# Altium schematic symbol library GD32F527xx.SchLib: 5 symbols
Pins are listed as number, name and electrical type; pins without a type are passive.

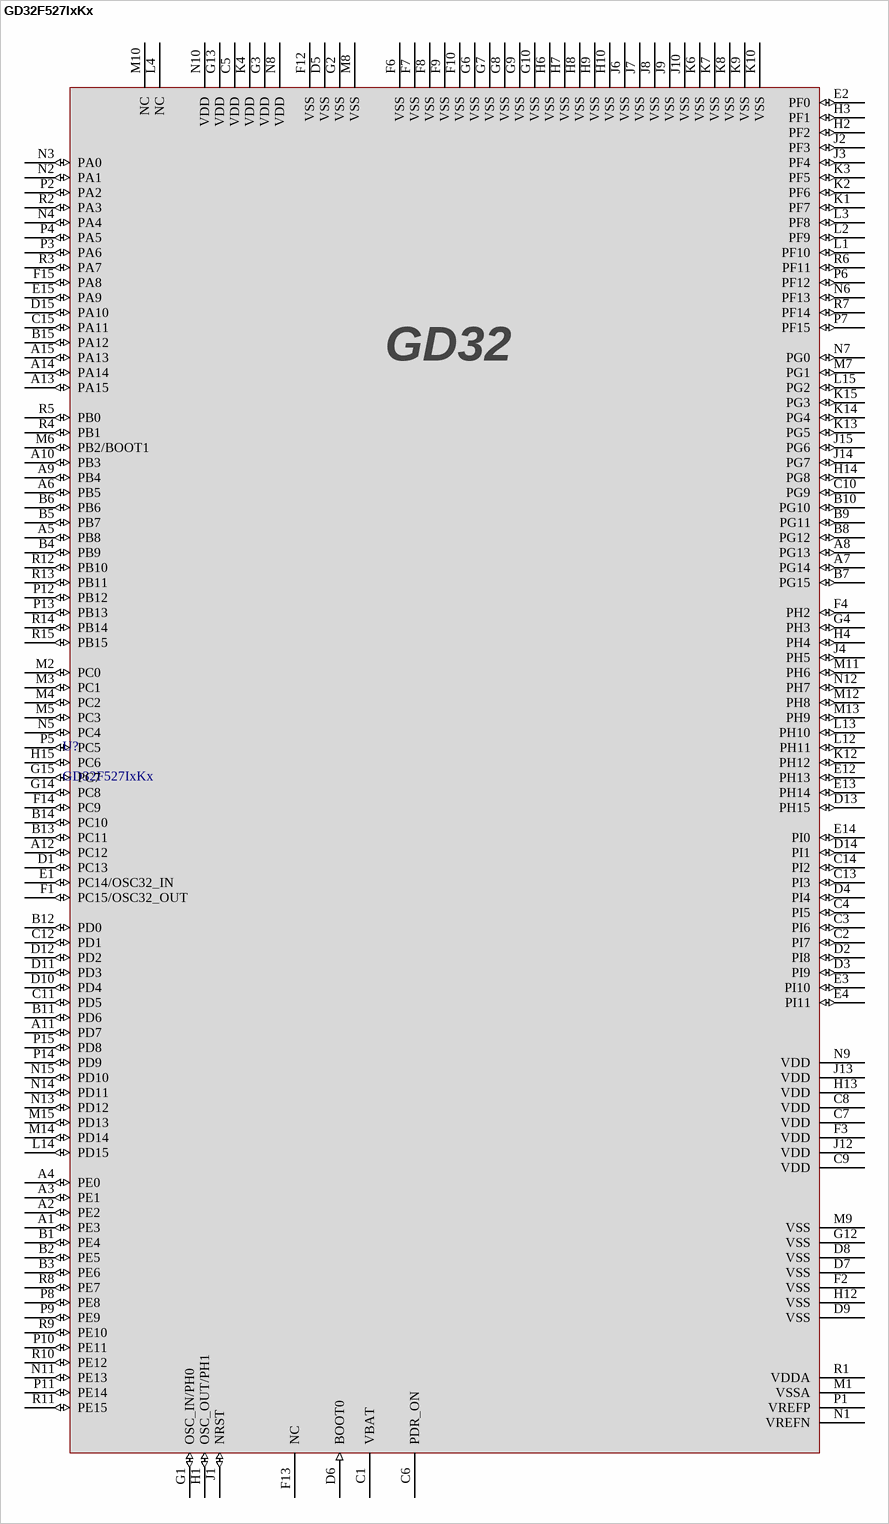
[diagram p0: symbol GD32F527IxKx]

## GD32F527IxKx
designator U?
footprint BGA176_10x10X0.89
pins: A1 PE3 (io), A2 PE2 (io), A3 PE1 (io), A4 PE0 (io), A5 PB8 (io), A6 PB5 (io), A7 PG14 (io), A8 PG13 (io), A9 PB4 (io), A10 PB3 (io), A11 PD7 (io), A12 PC12 (io), A13 PA15 (io), A14 PA14 (io), A15 PA13 (io), B1 PE4 (io), B2 PE5 (io), B3 PE6 (io), B4 PB9 (io), B5 PB7 (io), B6 PB6 (io), B7 PG15 (io), B8 PG12 (io), B9 PG11 (io), B10 PG10 (io), B11 PD6 (io), B12 PD0 (io), B13 PC11 (io), B14 PC10 (io), B15 PA12 (io), C1 VBAT (power), C2 PI7 (io), C3 PI6 (io), C4 PI5 (io), C5 VDD (power), C6 PDR_ON (power), C7 VDD (power), C8 VDD (power), C9 VDD (power), C10 PG9 (io), C11 PD5 (io), C12 PD1 (io), C13 PI3 (io), C14 PI2 (io), C15 PA11 (io), D1 PC13 (io), D2 PI8 (io), D3 PI9 (io), D4 PI4 (io), D5 VSS (power), D6 BOOT0 (in), D7 VSS (power), D8 VSS (power), D9 VSS (power), D10 PD4 (io), D11 PD3 (io), D12 PD2 (io), D13 PH15 (io), D14 PI1 (io), D15 PA10 (io), E1 PC14/OSC32_IN (io), E2 PF0 (io), E3 PI10 (io), E4 PI11 (io), E12 PH13 (io), E13 PH14 (io), E14 PI0 (io), E15 PA9 (io), F1 PC15/OSC32_OUT (io), F2 VSS (power), F3 VDD (power), F4 PH2 (io), F6 VSS (power), F7 VSS (power), F8 VSS (power), F9 VSS (power), F10 VSS (power), F12 VSS (power), F13 NC, F14 PC9 (io), F15 PA8 (io), G1 OSC_IN/PH0 (io), G2 VSS (power), G3 VDD (power), G4 PH3 (io), G6 VSS (power), G7 VSS (power), G8 VSS (power), G9 VSS (power), G10 VSS (power), G12 VSS (power), G13 VDD (power), G14 PC8 (io), G15 PC7 (io), H1 OSC_OUT/PH1 (io), H2 PF2 (io), H3 PF1 (io), H4 PH4 (io), H6 VSS (power), H7 VSS (power), H8 VSS (power), H9 VSS (power), H10 VSS (power), H12 VSS (power), H13 VDD (power), H14 PG8 (io), H15 PC6 (io), J1 NRST (io), J2 PF3 (io), J3 PF4 (io), J4 PH5 (io), J6 VSS (power), J7 VSS (power), J8 VSS (power), J9 VSS (power), J10 VSS (power), J12 VDD (power), J13 VDD (power), J14 PG7 (io), J15 PG6 (io), K1 PF7 (io), K2 PF6 (io), K3 PF5 (io), K4 VDD (power), K6 VSS (power), K7 VSS (power), K8 VSS (power), K9 VSS (power), K10 VSS (power), K12 PH12 (io), K13 PG5 (io), K14 PG4 (io), K15 PG3 (io), L1 PF10 (io), L2 PF9 (io), L3 PF8 (io), L4 NC (power), L12 PH11 (io), L13 PH10 (io), L14 PD15 (io), L15 PG2 (io), M1 VSSA (power), M2 PC0 (io), M3 PC1 (io), M4 PC2 (io), M5 PC3 (io), M6 PB2/BOOT1 (io), M7 PG1 (io), M8 VSS (power), M9 VSS (power), M10 NC, M11 PH6 (io), M12 PH8 (io), M13 PH9 (io), M14 PD14 (io), M15 PD13 (io), N1 VREFN (power), N2 PA1 (io), N3 PA0 (io), N4 PA4 (io), N5 PC4 (io), N6 PF13 (io), N7 PG0 (io), N8 VDD (power), N9 VDD (power), N10 VDD (power), N11 PE13 (io), N12 PH7 (io), N13 PD12 (io), N14 PD11 (io), N15 PD10 (io), P1 VREFP (power), P2 PA2 (io), P3 PA6 (io), P4 PA5 (io), P5 PC5 (io), P6 PF12 (io), P7 PF15 (io), P8 PE8 (io), P9 PE9 (io), P10 PE11 (io), P11 PE14 (io), P12 PB12 (io), P13 PB13 (io), P14 PD9 (io), P15 PD8 (io), R1 VDDA (power), R2 PA3  (io), R3 PA7 (io), R4 PB1 (io), R5 PB0 (io), R6 PF11 (io), R7 PF14 (io), R8 PE7 (io), R9 PE10 (io), R10 PE12 (io), R11 PE15 (io), R12 PB10 (io), R13 PB11 (io), R14 PB14 (io), R15 PB15 (io)

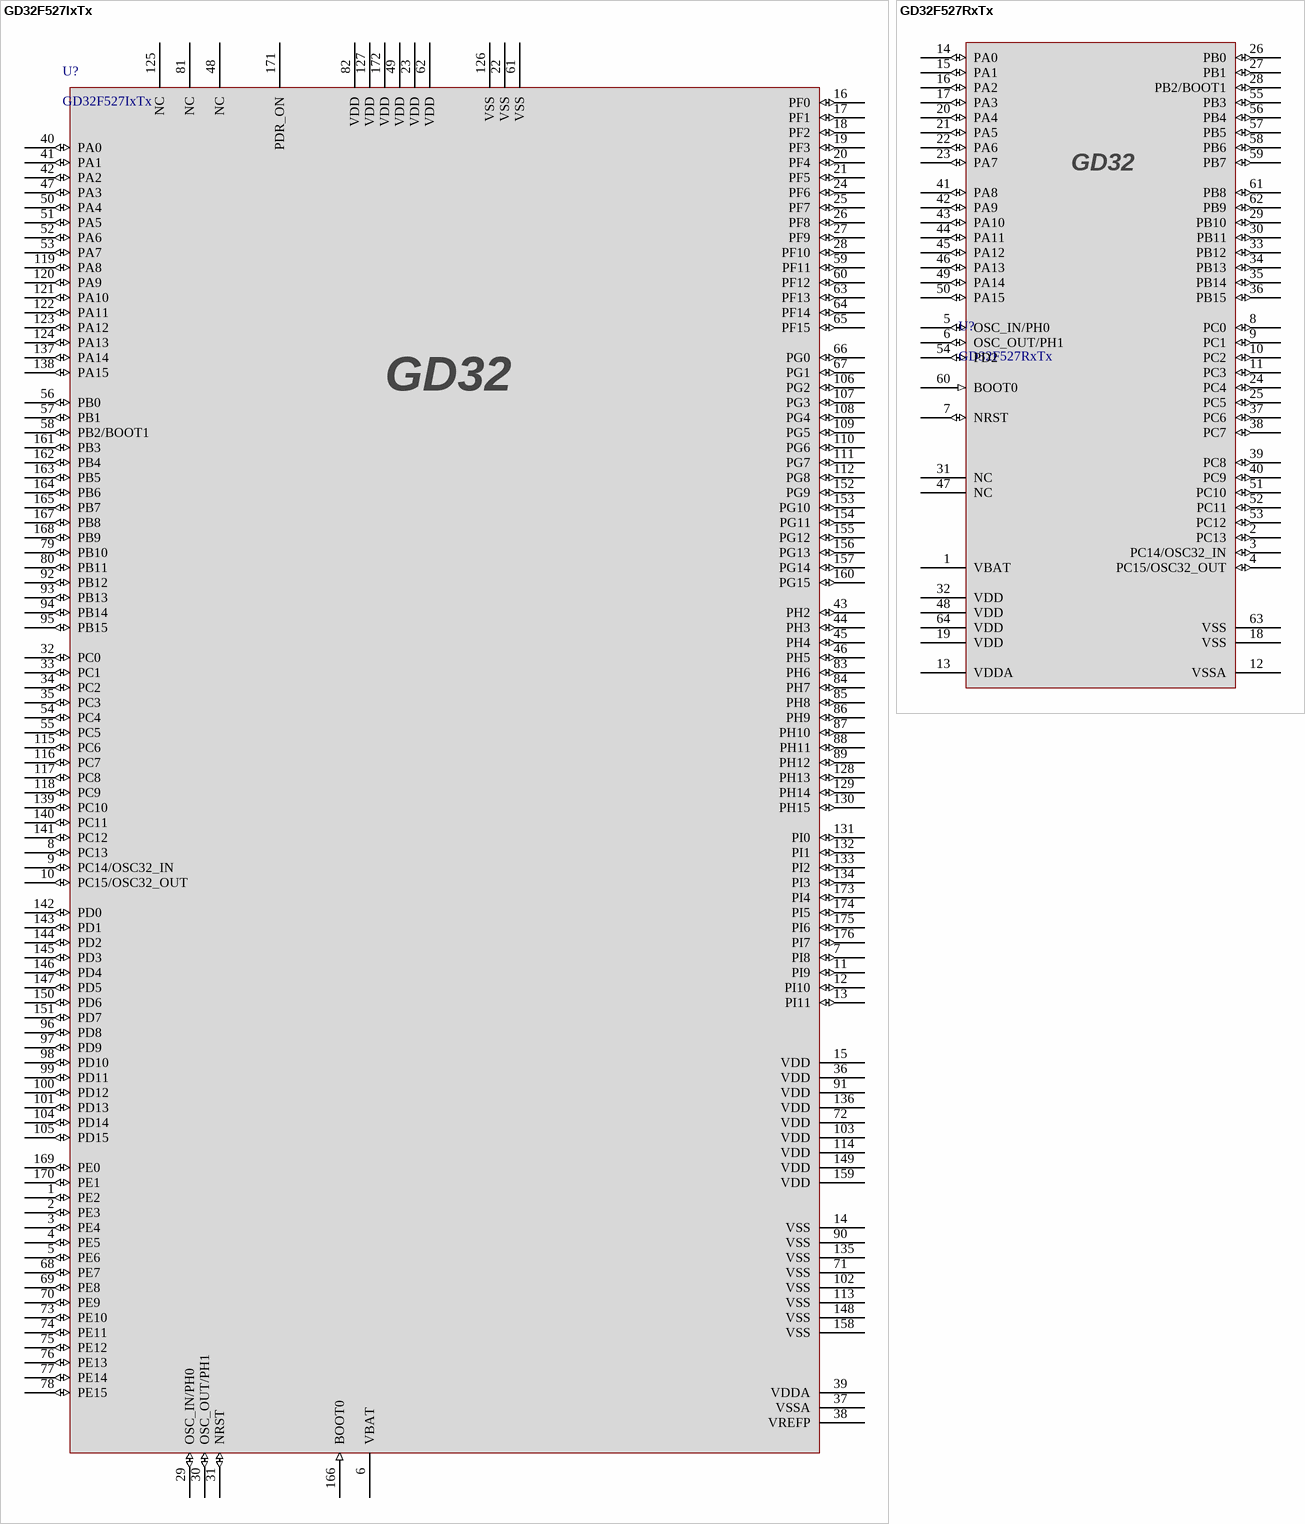
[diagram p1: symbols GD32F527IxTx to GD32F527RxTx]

## GD32F527IxTx
designator U?
footprint LQFP176_24x24X1.6
pins: 1 PE2 (io), 2 PE3 (io), 3 PE4 (io), 4 PE5 (io), 5 PE6 (io), 6 VBAT (power), 7 PI8 (io), 8 PC13 (io), 9 PC14/OSC32_IN (io), 10 PC15/OSC32_OUT (io), 11 PI9 (io), 12 PI10 (io), 13 PI11 (io), 14 VSS (power), 15 VDD (power), 16 PF0 (io), 17 PF1 (io), 18 PF2 (io), 19 PF3 (io), 20 PF4 (io), 21 PF5 (io), 22 VSS (power), 23 VDD (power), 24 PF6 (io), 25 PF7 (io), 26 PF8 (io), 27 PF9 (io), 28 PF10 (io), 29 OSC_IN/PH0 (io), 30 OSC_OUT/PH1 (io), 31 NRST (io), 32 PC0 (io), 33 PC1 (io), 34 PC2 (io), 35 PC3 (io), 36 VDD (power), 37 VSSA (power), 38 VREFP (power), 39 VDDA (power), 40 PA0 (io), 41 PA1 (io), 42 PA2 (io), 43 PH2 (io), 44 PH3 (io), 45 PH4 (io), 46 PH5 (io), 47 PA3  (io), 48 NC (power), 49 VDD (power), 50 PA4 (io), 51 PA5 (io), 52 PA6 (io), 53 PA7 (io), 54 PC4 (io), 55 PC5 (io), 56 PB0 (io), 57 PB1 (io), 58 PB2/BOOT1 (io), 59 PF11 (io), 60 PF12 (io), 61 VSS (power), 62 VDD (power), 63 PF13 (io), 64 PF14 (io), 65 PF15 (io), 66 PG0 (io), 67 PG1 (io), 68 PE7 (io), 69 PE8 (io), 70 PE9 (io), 71 VSS (power), 72 VDD (power), 73 PE10 (io), 74 PE11 (io), 75 PE12 (io), 76 PE13 (io), 77 PE14 (io), 78 PE15 (io), 79 PB10 (io), 80 PB11 (io), 81 NC, 82 VDD (power), 83 PH6 (io), 84 PH7 (io), 85 PH8 (io), 86 PH9 (io), 87 PH10 (io), 88 PH11 (io), 89 PH12 (io), 90 VSS (power), 91 VDD (power), 92 PB12 (io), 93 PB13 (io), 94 PB14 (io), 95 PB15 (io), 96 PD8 (io), 97 PD9 (io), 98 PD10 (io), 99 PD11 (io), 100 PD12 (io), 101 PD13 (io), 102 VSS (power), 103 VDD (power), 104 PD14 (io), 105 PD15 (io), 106 PG2 (io), 107 PG3 (io), 108 PG4 (io), 109 PG5 (io), 110 PG6 (io), 111 PG7 (io), 112 PG8 (io), 113 VSS (power), 114 VDD (power), 115 PC6 (io), 116 PC7 (io), 117 PC8 (io), 118 PC9 (io), 119 PA8 (io), 120 PA9 (io), 121 PA10 (io), 122 PA11 (io), 123 PA12 (io), 124 PA13 (io), 125 NC, 126 VSS (power), 127 VDD (power), 128 PH13 (io), 129 PH14 (io), 130 PH15 (io), 131 PI0 (io), 132 PI1 (io), 133 PI2 (io), 134 PI3 (io), 135 VSS (power), 136 VDD (power), 137 PA14 (io), 138 PA15 (io), 139 PC10 (io), 140 PC11 (io), 141 PC12 (io), 142 PD0 (io), 143 PD1 (io), 144 PD2 (io), 145 PD3 (io), 146 PD4 (io), 147 PD5 (io), 148 VSS (power), 149 VDD (power), 150 PD6 (io), 151 PD7 (io), 152 PG9 (io), 153 PG10 (io), 154 PG11 (io), 155 PG12 (io), 156 PG13 (io), 157 PG14 (io), 158 VSS (power), 159 VDD (power), 160 PG15 (io), 161 PB3 (io), 162 PB4 (io), 163 PB5 (io), 164 PB6 (io), 165 PB7 (io), 166 BOOT0 (in), 167 PB8 (io), 168 PB9 (io), 169 PE0 (io), 170 PE1 (io), 171 PDR_ON (power), 172 VDD (power), 173 PI4 (io), 174 PI5 (io), 175 PI6 (io), 176 PI7 (io)

## GD32F527RxTx
designator U?
footprint LQPF64_10x10x1.6
pins: 1 VBAT (power), 2 PC13 (io), 3 PC14/OSC32_IN (io), 4 PC15/OSC32_OUT (io), 5 OSC_IN/PH0 (io), 6 OSC_OUT/PH1 (io), 7 NRST (io), 8 PC0 (io), 9 PC1 (io), 10 PC2 (io), 11 PC3 (io), 12 VSSA (power), 13 VDDA (power), 14 PA0 (io), 15 PA1 (io), 16 PA2 (io), 17 PA3 (io), 18 VSS (power), 19 VDD (power), 20 PA4 (io), 21 PA5 (io), 22 PA6 (io), 23 PA7 (io), 24 PC4 (io), 25 PC5 (io), 26 PB0 (io), 27 PB1 (io), 28 PB2/BOOT1 (io), 29 PB10 (io), 30 PB11 (io), 31 NC, 32 VDD (power), 33 PB12 (io), 34 PB13 (io), 35 PB14 (io), 36 PB15 (io), 37 PC6 (io), 38 PC7 (io), 39 PC8 (io), 40 PC9 (io), 41 PA8 (io), 42 PA9 (io), 43 PA10 (io), 44 PA11 (io), 45 PA12 (io), 46 PA13 (io), 47 NC, 48 VDD (power), 49 PA14 (io), 50 PA15 (io), 51 PC10 (io), 52 PC11 (io), 53 PC12 (io), 54 PD2 (io), 55 PB3 (io), 56 PB4 (io), 57 PB5 (io), 58 PB6 (io), 59 PB7 (io), 60 BOOT0 (in), 61 PB8 (io), 62 PB9 (io), 63 VSS (power), 64 VDD (power)

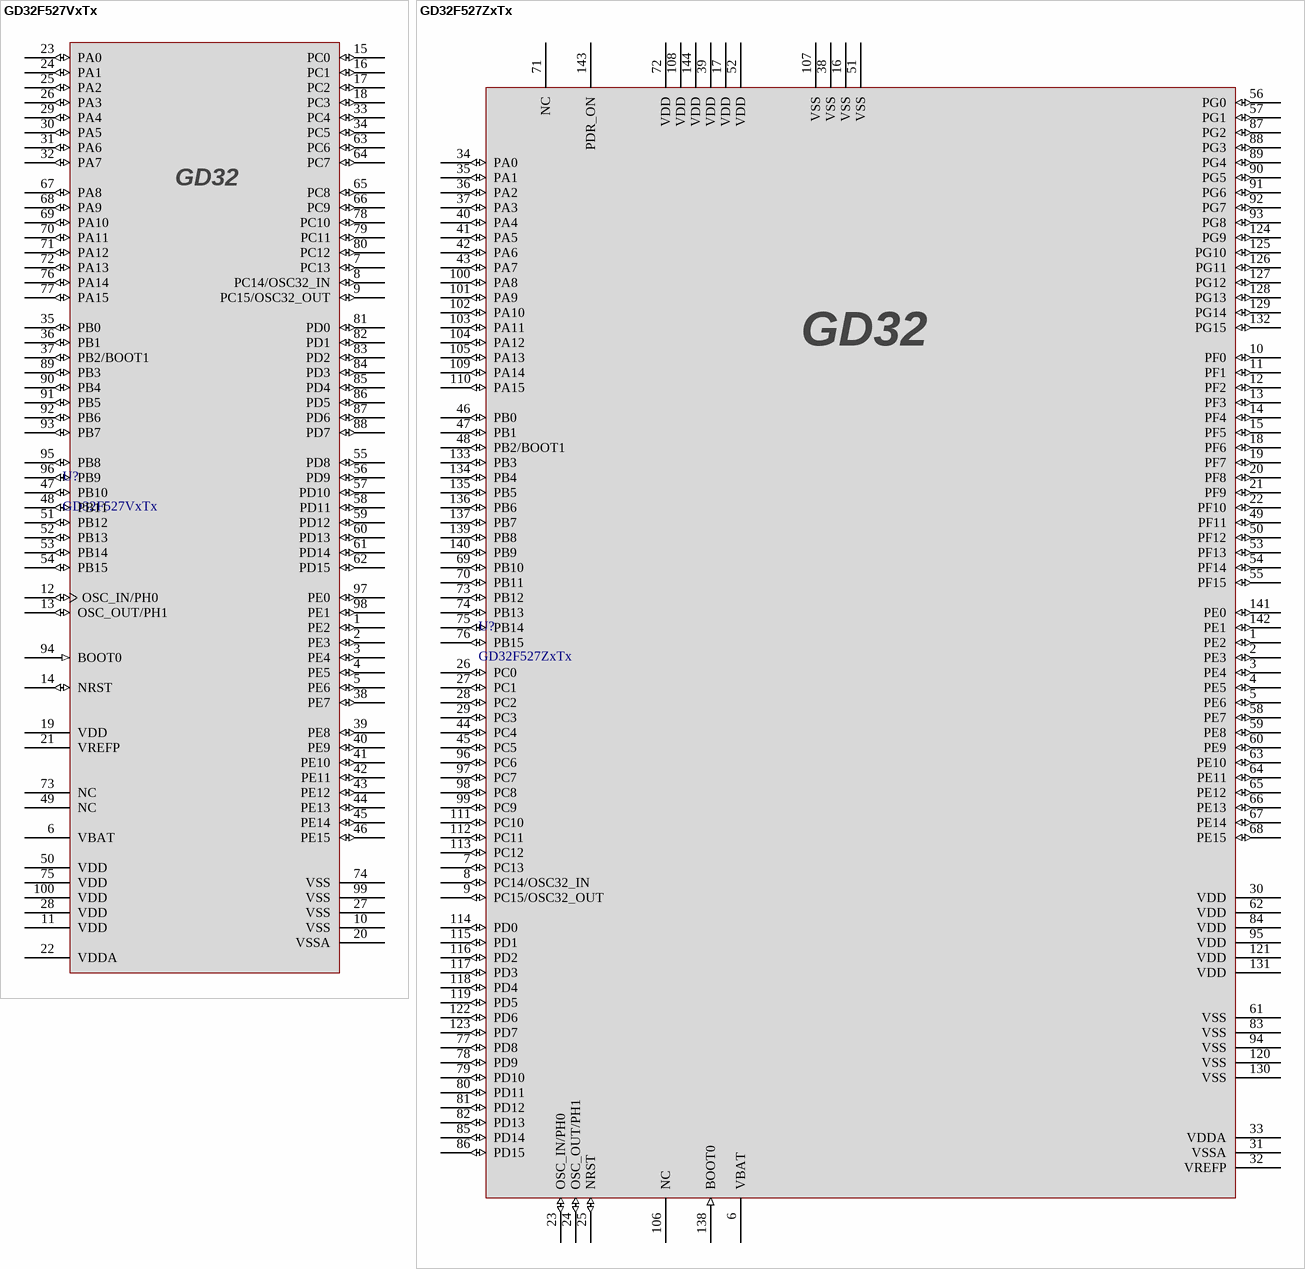
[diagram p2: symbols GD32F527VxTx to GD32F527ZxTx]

## GD32F527VxTx
designator U?
footprint LQFP100_14x14x1.6
pins: 1 PE2 (io), 2 PE3 (io), 3 PE4 (io), 4 PE5 (io), 5 PE6 (io), 6 VBAT (power), 7 PC13 (io), 8 PC14/OSC32_IN (io), 9 PC15/OSC32_OUT (io), 10 VSS (power), 11 VDD (power), 12 OSC_IN/PH0 (io), 13 OSC_OUT/PH1 (io), 14 NRST (io), 15 PC0 (io), 16 PC1 (io), 17 PC2 (io), 18 PC3 (io), 19 VDD (power), 20 VSSA (power), 21 VREFP (power), 22 VDDA (power), 23 PA0 (io), 24 PA1 (io), 25 PA2 (io), 26 PA3 (io), 27 VSS (power), 28 VDD (power), 29 PA4 (io), 30 PA5 (io), 31 PA6 (io), 32 PA7 (io), 33 PC4 (io), 34 PC5 (io), 35 PB0 (io), 36 PB1 (io), 37 PB2/BOOT1 (io), 38 PE7 (io), 39 PE8 (io), 40 PE9 (io), 41 PE10 (io), 42 PE11 (io), 43 PE12 (io), 44 PE13 (io), 45 PE14 (io), 46 PE15 (io), 47 PB10 (io), 48 PB11 (io), 49 NC, 50 VDD (power), 51 PB12 (io), 52 PB13 (io), 53 PB14 (io), 54 PB15 (io), 55 PD8 (io), 56 PD9 (io), 57 PD10 (io), 58 PD11 (io), 59 PD12 (io), 60 PD13 (io), 61 PD14 (io), 62 PD15 (io), 63 PC6 (io), 64 PC7 (io), 65 PC8 (io), 66 PC9 (io), 67 PA8 (io), 68 PA9 (io), 69 PA10 (io), 70 PA11 (io), 71 PA12 (io), 72 PA13 (io), 73 NC, 74 VSS (power), 75 VDD (power), 76 PA14 (io), 77 PA15 (io), 78 PC10 (io), 79 PC11 (io), 80 PC12 (io), 81 PD0 (io), 82 PD1 (io), 83 PD2 (io), 84 PD3 (io), 85 PD4 (io), 86 PD5 (io), 87 PD6 (io), 88 PD7 (io), 89 PB3 (io), 90 PB4 (io), 91 PB5 (io), 92 PB6 (io), 93 PB7 (io), 94 BOOT0 (in), 95 PB8 (io), 96 PB9 (io), 97 PE0 (io), 98 PE1 (io), 99 VSS (power), 100 VDD (power)

## GD32F527ZxTx
designator U?
footprint LQFP144_20x20X1.6
pins: 1 PE2 (io), 2 PE3 (io), 3 PE4 (io), 4 PE5 (io), 5 PE6 (io), 6 VBAT (power), 7 PC13 (io), 8 PC14/OSC32_IN (io), 9 PC15/OSC32_OUT (io), 10 PF0 (io), 11 PF1 (io), 12 PF2 (io), 13 PF3 (io), 14 PF4 (io), 15 PF5 (io), 16 VSS (power), 17 VDD (power), 18 PF6 (io), 19 PF7 (io), 20 PF8 (io), 21 PF9 (io), 22 PF10 (io), 23 OSC_IN/PH0 (io), 24 OSC_OUT/PH1 (io), 25 NRST (io), 26 PC0 (io), 27 PC1 (io), 28 PC2 (io), 29 PC3 (io), 30 VDD (power), 31 VSSA (power), 32 VREFP (power), 33 VDDA (power), 34 PA0 (io), 35 PA1 (io), 36 PA2 (io), 37 PA3  (io), 38 VSS (power), 39 VDD (power), 40 PA4 (io), 41 PA5 (io), 42 PA6 (io), 43 PA7  (io), 44 PC4 (io), 45 PC5 (io), 46 PB0 (io), 47 PB1 (io), 48 PB2/BOOT1 (io), 49 PF11 (io), 50 PF12 (io), 51 VSS (power), 52 VDD (power), 53 PF13 (io), 54 PF14 (io), 55 PF15 (io), 56 PG0 (io), 57 PG1 (io), 58 PE7 (io), 59 PE8 (io), 60 PE9 (io), 61 VSS (power), 62 VDD (power), 63 PE10 (io), 64 PE11 (io), 65 PE12 (io), 66 PE13 (io), 67 PE14 (io), 68 PE15 (io), 69 PB10 (io), 70 PB11 (io), 71 NC, 72 VDD (power), 73 PB12 (io), 74 PB13 (io), 75 PB14 (io), 76 PB15 (io), 77 PD8 (io), 78 PD9 (io), 79 PD10 (io), 80 PD11 (io), 81 PD12 (io), 82 PD13 (io), 83 VSS (power), 84 VDD (power), 85 PD14 (io), 86 PD15 (io), 87 PG2 (io), 88 PG3 (io), 89 PG4 (io), 90 PG5 (io), 91 PG6 (io), 92 PG7 (io), 93 PG8 (io), 94 VSS (power), 95 VDD (power), 96 PC6 (io), 97 PC7 (io), 98 PC8 (io), 99 PC9 (io), 100 PA8 (io), 101 PA9 (io), 102 PA10 (io), 103 PA11 (io), 104 PA12  (io), 105 PA13 (io), 106 NC, 107 VSS (power), 108 VDD (power), 109 PA14 (io), 110 PA15 (io), 111 PC10 (io), 112 PC11 (io), 113 PC12 (io), 114 PD0 (io), 115 PD1 (io), 116 PD2 (io), 117 PD3 (io), 118 PD4 (io), 119 PD5 (io), 120 VSS (power), 121 VDD (power), 122 PD6 (io), 123 PD7 (io), 124 PG9 (io), 125 PG10 (io), 126 PG11 (io), 127 PG12 (io), 128 PG13 (io), 129 PG14 (io), 130 VSS (power), 131 VDD (power), 132 PG15 (io), 133 PB3 (io), 134 PB4 (io), 135 PB5 (io), 136 PB6 (io), 137 PB7 (io), 138 BOOT0 (in), 139 PB8 (io), 140 PB9 (io), 141 PE0 (io), 142 PE1 (io), 143 PDR_ON (power), 144 VDD (power)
